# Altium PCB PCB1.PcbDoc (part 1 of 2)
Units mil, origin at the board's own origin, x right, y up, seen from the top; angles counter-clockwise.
Board outline 3935 x 3935 mil, 2 copper layers (Top Layer, Bottom Layer); 151 components, 133 nets, 573 pads, 224 vias.
Unrouted connection lines stored in the file: 1.
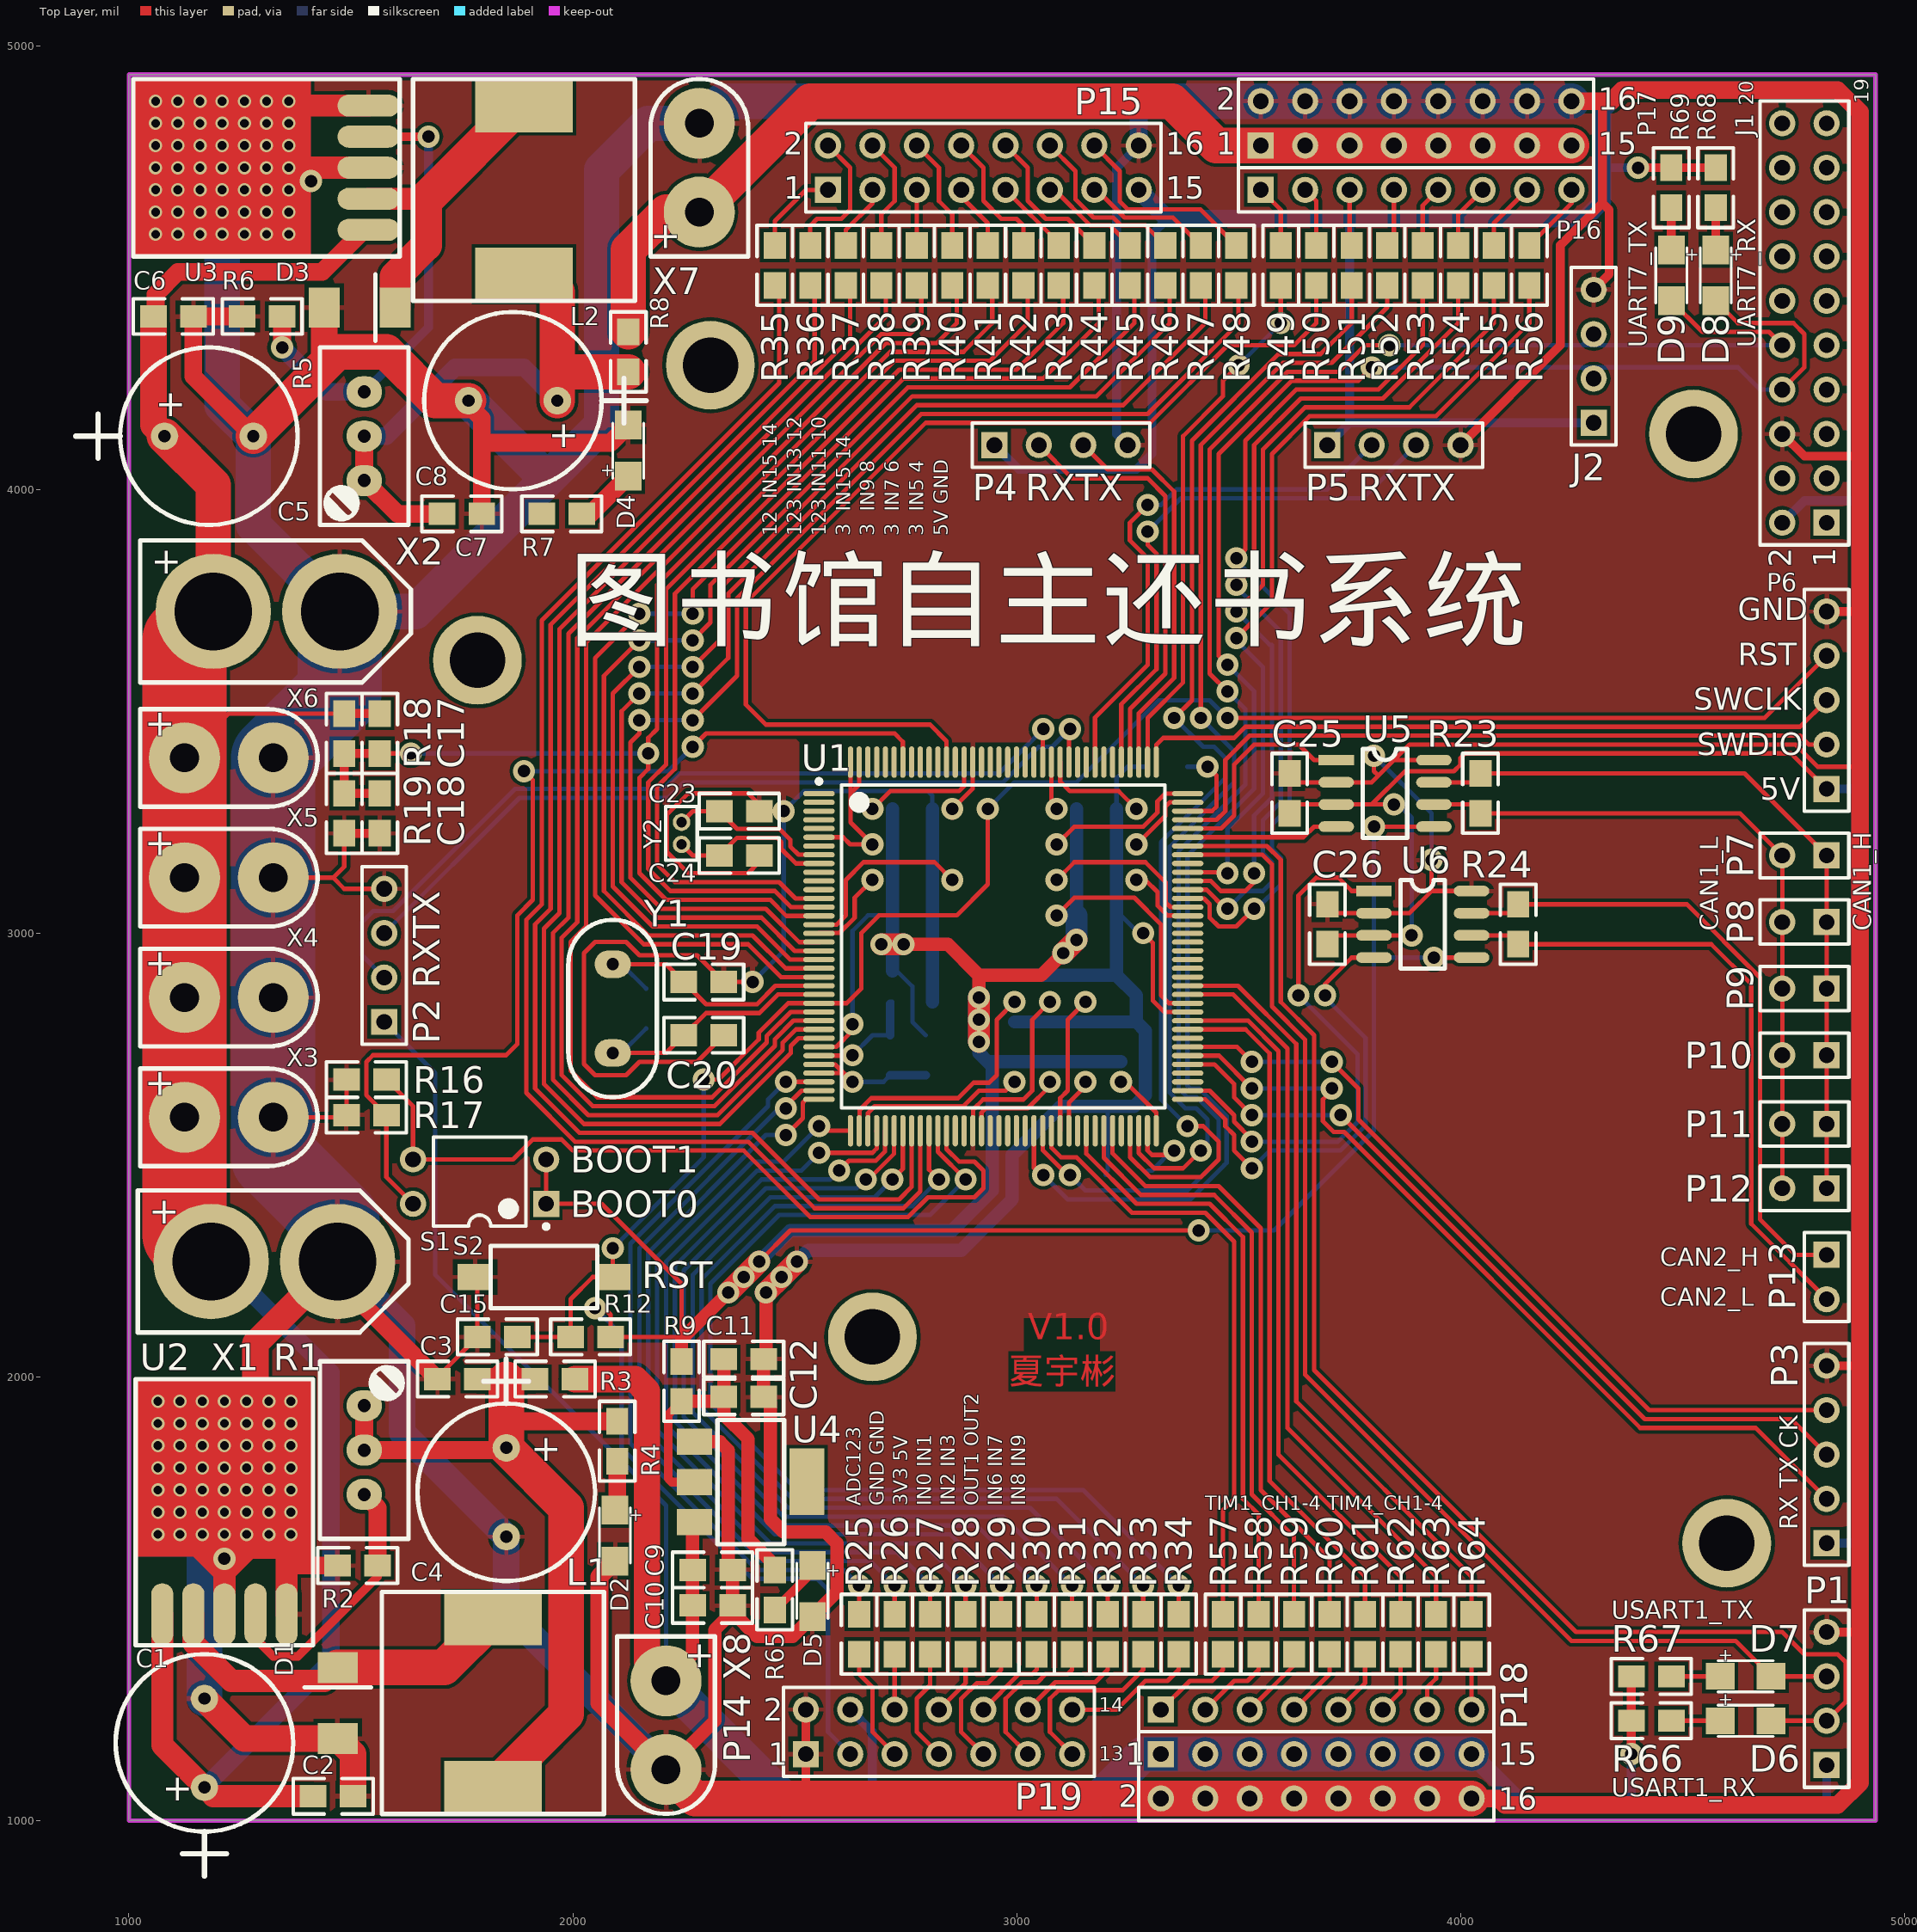
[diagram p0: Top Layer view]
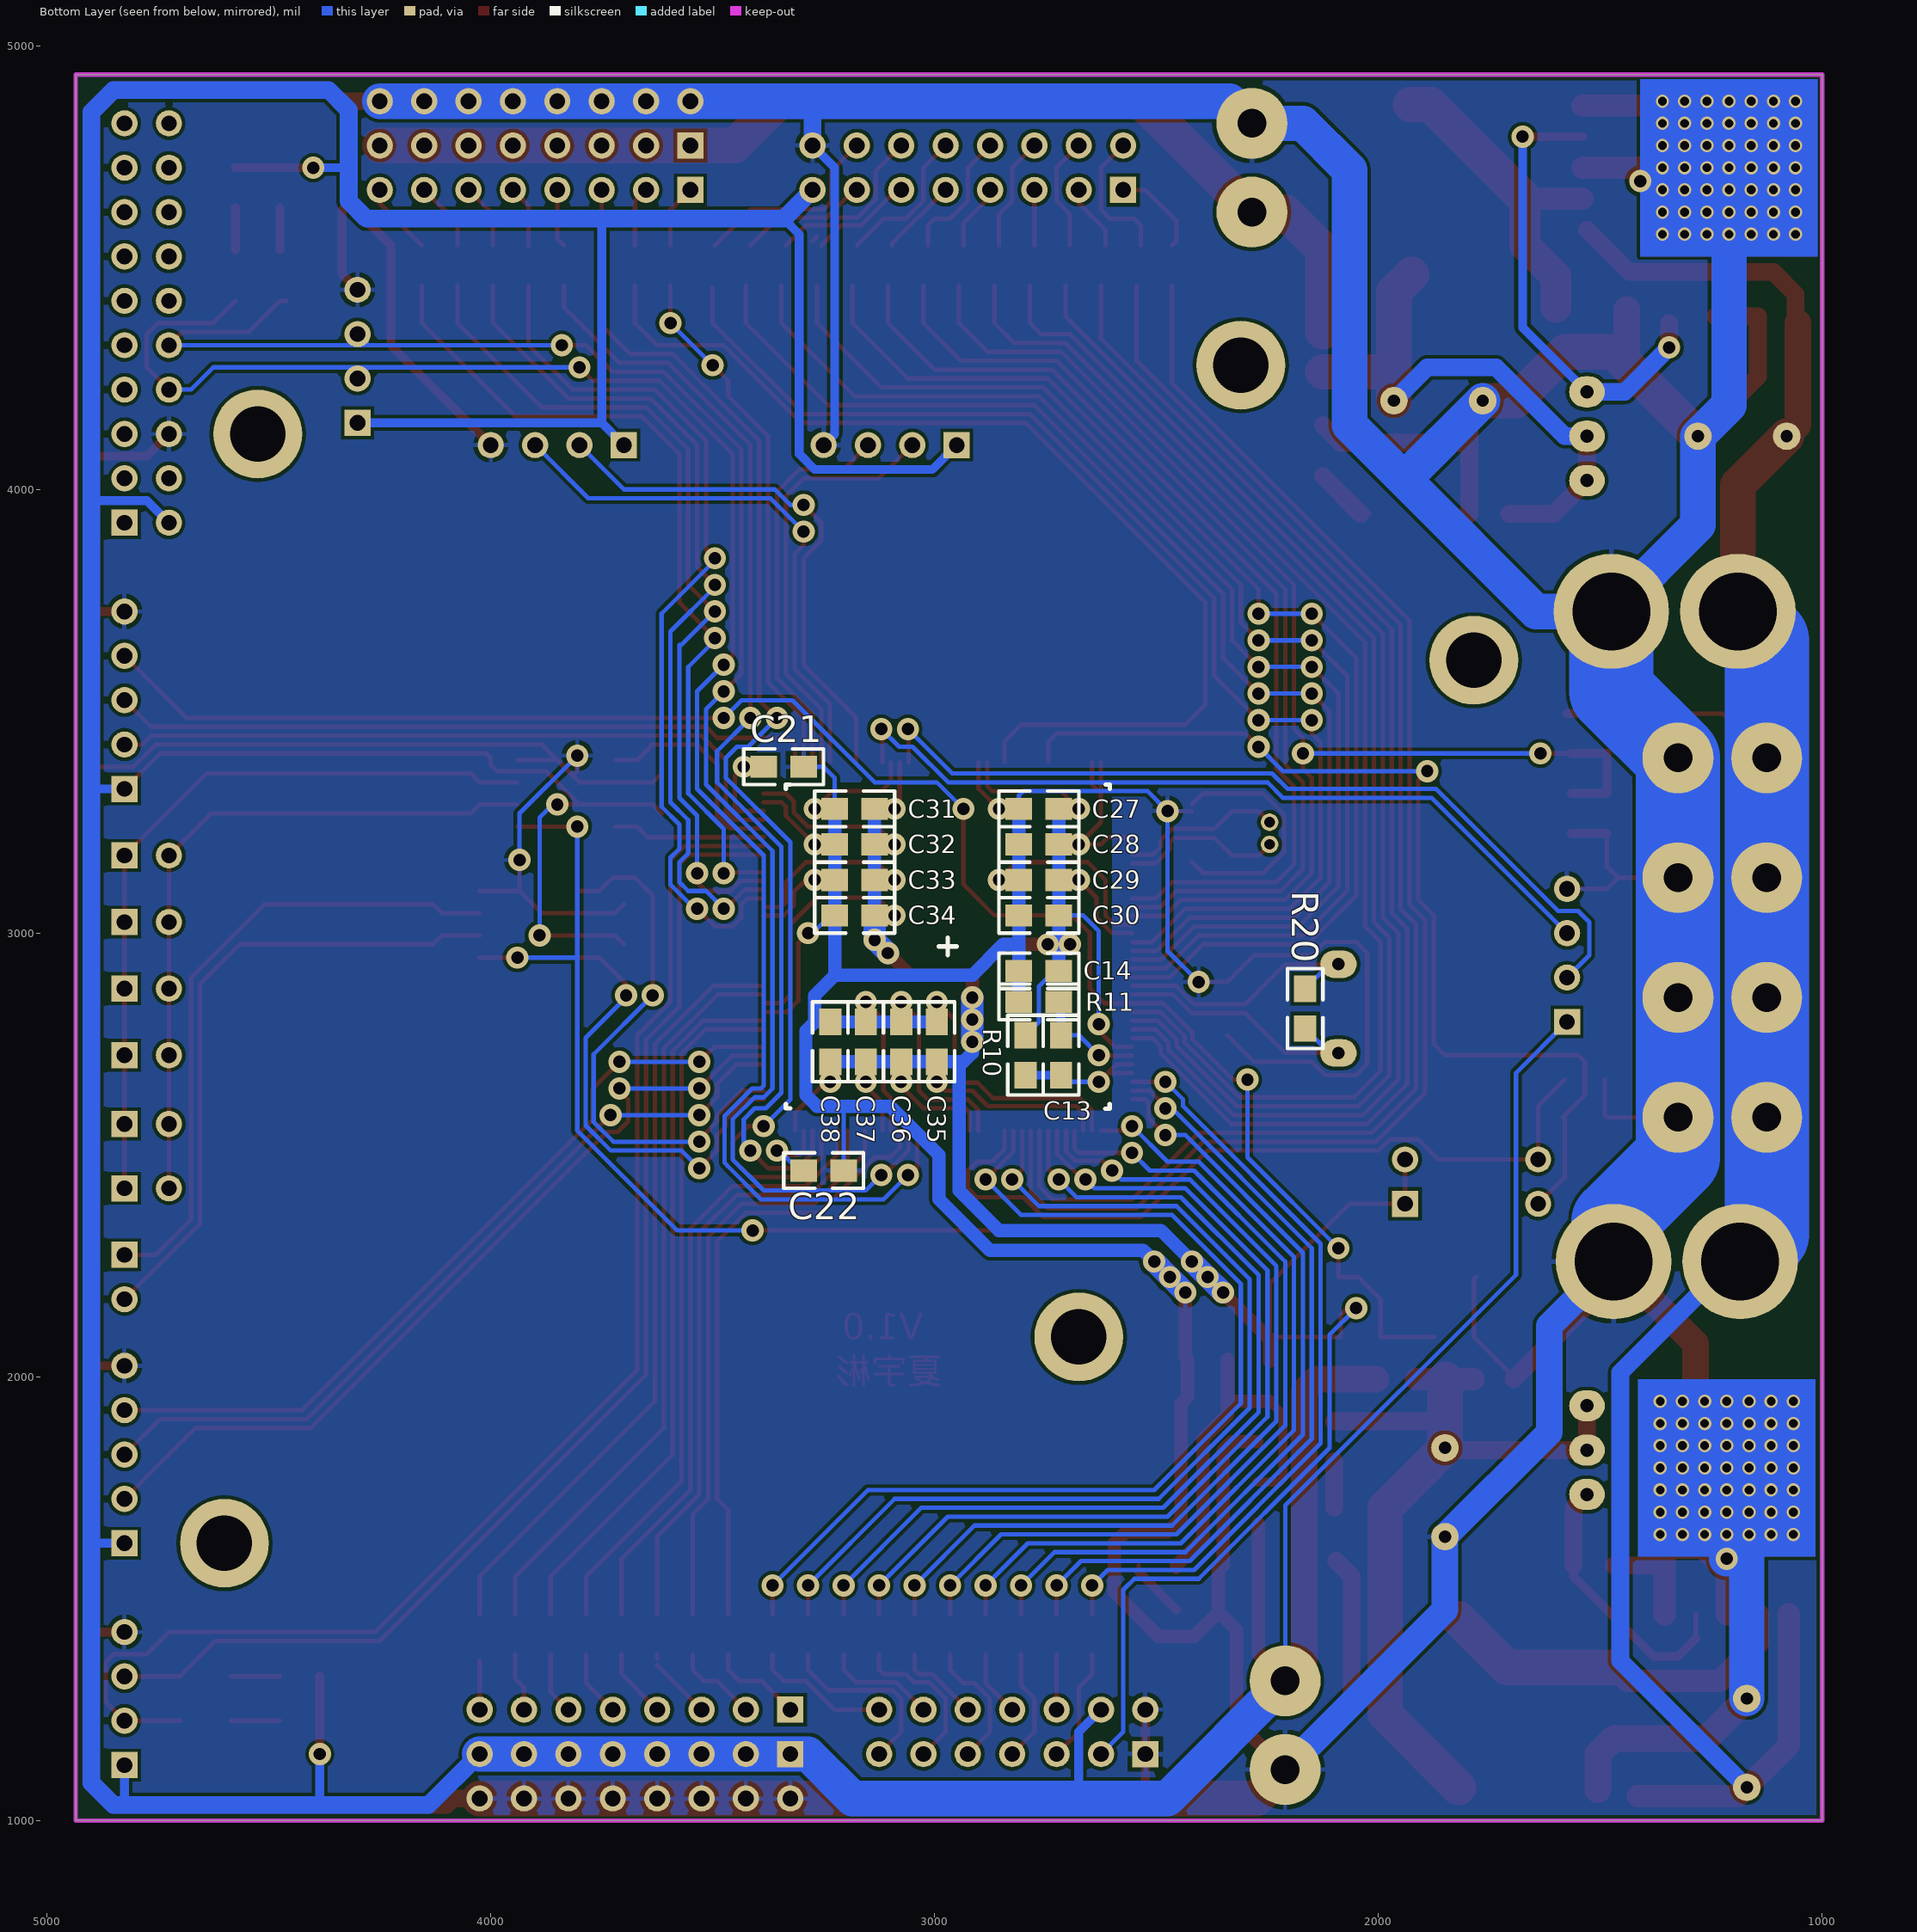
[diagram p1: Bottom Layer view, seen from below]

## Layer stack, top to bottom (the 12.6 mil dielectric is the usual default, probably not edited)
Top Solder: solder mask 0.4, Solder Resist, Dk 3.5
Top Layer: signal copper 1.4
Dielectric 1: dielectric 12.6, FR-4, Dk 4.8
Bottom Layer: signal copper 1.4
Bottom Solder: solder mask 0.4, Solder Resist, Dk 3.5

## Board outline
1000,1000 4935,1000 4935,4935 1000,4935

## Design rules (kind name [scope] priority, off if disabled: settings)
Clearance [All] p1: gap=8
PolygonConnect [All] p1: connectstyle=Relief reliefconductorwidth=10 reliefentries=4 polygonreliefangle="90 Angle" airgapwidth=10
RoutingVias [All] p1: holewidth=28 width=50 viastyle="Through Hole" minholewidth=28 minwidth=50 maxholewidth=28 maxwidth=50
SolderMaskExpansion [All] p1: expansion=4
Width [All] p1: maxlimit=10 minlimit=10 preferedwidth=10
30 further rules are at their usual default settings.

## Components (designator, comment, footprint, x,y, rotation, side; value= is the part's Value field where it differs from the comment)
C1 "Cap Pol1" RB-.2/.4 1170,1075 r270 top
C2 "Cap" 0805 1505,1055 r180 top
C3 "Cap" 0805 1785,1995 r180 top
C4 "Cap Pol1" RB-.2/.4 1850,1840 r90 top
C5 "Cap Pol1" RB-.2/.4 1080,4120 r180 top
C6 "Cap" 0805 1145,4390 r180 top
C7 "Cap" 0805 1705,3945 r0 top
C8 "Cap Pol1" RB-.2/.4 1965,4200 r0 top
C9 "Cap Pol1" 0805 2270,1565 r0 top
C10 "Cap" 0805 2360,1485 r180 top
C11 "Cap Pol1" 0805 2340,2040 r0 top
C12 "Cap" 0805 2430,1955 r180 top
C13 "Cap" 0805 2715,2770 r270 bottom
C14 "Cap" 0805 2810,2915 r180 bottom
C15 "Cap" 0805 1875,2090 r180 top
C17 "Cap" 0805 1565,3405 r90 top
C18 "Cap" 0805 1565,3225 r90 top
C19 "Cap" 0805 2250,2890 r0 top
C20 "Cap" 0805 2250,2770 r0 top
C21 "Cap" 0805 3295,3375 r0 bottom
C22 "Cap" 0805 3205,2465 r0 bottom
C23 "12pF" 0805 2420,3275 r180 top
C24 "12pF" 0805 2420,3175 r180 top
C25 "Cap" 0805 3615,3270 r90 top
C26 "Cap" 0805 3700,2975 r90 top
C27 "Cap" 0805 2810,3280 r180 bottom
C28 "Cap" 0805 2810,3200 r180 bottom
C29 "Cap" 0805 2810,3120 r180 bottom
C30 "Cap" 0805 2810,3040 r180 bottom
C31 "Cap" 0805 3225,3280 r180 bottom
C32 "Cap" 0805 3225,3200 r180 bottom
C33 "Cap" 0805 3225,3120 r180 bottom
C34 "Cap" 0805 3225,3040 r180 bottom
C35 "Cap" 0805 2995,2800 r270 bottom
C36 "Cap" 0805 3075,2800 r270 bottom
C37 "Cap" 0805 3155,2800 r270 bottom
C38 "Cap" 0805 3235,2800 r270 bottom
D1 "SS54" DO-214AA 1515,1150 r90 top
D2 "LED_RED" 1206_LED 2060,1705 r270 top
D3 "SS54" DO-214AA 1405,4365 r0 top
D4 "LED_RED" 1206_LED 2160,4025 r90 top
D5 "LED_RED" 1206_LED 2505,1580 r270 top
D6 "LED_RED" 1206_LED 4580,1190 r0 top
D7 "LED_RED" 1206_LED 4580,1290 r0 top
D8 "LED_RED" 1206_LED 4540,4545 r270 top
D9 "LED_RED" 1206_LED 4440,4545 r270 top
J1 "Header 10X2H" HDR2X10 4825,3925 r90 top
J2 "USART3" HDR1X4 4300,4150 r90 top
L1 "Inductor" 12*12*7贴片电感 1570,1015 r0 top
L2 "Inductor" 12*12*7贴片电感 1640,4425 r0 top
P1 "USART1" HDR1X4 4825,1125 r90 top
P2 "USART2" HDR1X4 1575,2800 r90 top
P3 "Header 5" HDR1X5 4825,1625 r90 top
P4 "USART3" HDR1X4 2950,4100 r0 top
P5 "USART3" HDR1X4 3700,4100 r0 top
P6 "Header 5" HDR1X5 4825,3325 r90 top
P7 "CAN1" HDR1X2 4825,3175 r180 top
P8 "CAN1" HDR1X2 4825,3025 r180 top
P9 "CAN1" HDR1X2 4825,2875 r180 top
P10 "CAN1" HDR1X2 4825,2725 r180 top
P11 "CAN1" HDR1X2 4825,2570 r180 top
P12 "CAN1" HDR1X2 4825,2425 r180 top
P13 "CAN2" HDR1X2 4825,2275 r270 top
P14 "Header 7X2" HDR2X7 2525,1150 r0 top
P15 "Header 8X2" HDR2X8#1 2575,4675 r0 top
P16 "Header 8" HDR1X8 3550,4675 r0 top
P17 "Header 8X2" HDR2X8#1 3550,4775 r0 top
P18 "Header 8" HDR1X8 3325,1250 r0 top
P19 "Header 8X2" HDR2X8#2 3325,1150 r0 top
R1 "Res Tap" 3296 1530,1835 r90 top
R2 "Res2" 0805 1470,1575 r0 top
R3 "Res2" 0805 2100,1900 r270 top
R4 "Res2" 0805 1915,1995 r0 top
R5 "Res Tap" 3296 1530,4120 r270 top
R6 "Res2" 0805 1255,4390 r0 top
R7 "Res2" 0805 1930,3945 r0 top
R8 "Res2" 0805 2125,4265 r90 top
R9 "Res2" 0805 2245,1945 r90 top
R10 "Res2" 0805 2795,2680 r90 bottom
R11 "Res2" 0805 2720,2845 r0 bottom
R12 "Res2" 0805 1995,2090 r0 top
R16 "Res2" 0805 1490,2670 r0 top
R17 "Res2" 0805 1490,2590 r0 top
R18 "9K" 0805 1485,3405 r90 top
R19 "1K" 0805 1485,3225 r90 top
R20 "Res2" 0805 2165,2785 r90 bottom
R23 "Res2" 0805 4045,3270 r90 top
R24 "120R" 0805 4130,2975 r90 top
R25 "100R" 0805 2645,1465 r270 top
R26 "100R" 0805 2725,1375 r90 top
R27 "100R" 0805 2805,1465 r270 top
R28 "100R" 0805 2885,1375 r90 top
R29 "100R" 0805 2965,1465 r270 top
R30 "100R" 0805 3045,1375 r90 top
R31 "100R" 0805 3125,1465 r270 top
R32 "100R" 0805 3205,1375 r90 top
R33 "100R" 0805 3285,1465 r270 top
R34 "100R" 0805 3365,1375 r90 top
R35 "100R" 0805 2455,4460 r90 top
R36 "100R" 0805 2535,4550 r270 top
R37 "100R" 0805 2615,4460 r90 top
R38 "100R" 0805 2695,4550 r270 top
R39 "100R" 0805 2775,4460 r90 top
R40 "100R" 0805 2855,4550 r270 top
R41 "100R" 0805 2935,4460 r90 top
R42 "100R" 0805 3015,4550 r270 top
R43 "100R" 0805 3095,4460 r90 top
R44 "100R" 0805 3175,4550 r270 top
R45 "100R" 0805 3255,4460 r90 top
R46 "100R" 0805 3335,4550 r270 top
R47 "100R" 0805 3415,4460 r90 top
R48 "100R" 0805 3495,4550 r270 top
R49 "100R" 0805 3595,4460 r90 top
R50 "100R" 0805 3675,4460 r90 top
R51 "100R" 0805 3755,4460 r90 top
R52 "100R" 0805 3835,4460 r90 top
R53 "100R" 0805 3915,4460 r90 top
R54 "100R" 0805 3995,4460 r90 top
R55 "100R" 0805 4075,4460 r90 top
R56 "100R" 0805 4155,4460 r90 top
R57 "100R" 0805 3465,1465 r270 top
R58 "100R" 0805 3545,1465 r270 top
R59 "100R" 0805 3625,1465 r270 top
R60 "100R" 0805 3705,1465 r270 top
R61 "100R" 0805 3785,1465 r270 top
R62 "100R" 0805 3865,1465 r270 top
R63 "100R" 0805 3945,1465 r270 top
R64 "100R" 0805 4025,1465 r270 top
R65 "Res2" 0805 2455,1475 r90 top
R66 "Res2" 0805 4475,1225 r180 top
R67 "Res2" 0805 4475,1325 r180 top
R68 "Res2" 0805 4575,4635 r90 top
R69 "Res2" 0805 4475,4635 r90 top
S1 "SW DIP-2" DIP-4 1790,2440 r180 top
S2 "SW-PB" "3*6 开关" 1815,2155 r0 top
U1 "STM32F429ZGT6" STM-LQFP144_N 2970,2970 r0 top locked
U2 "LM2596S-ADJ" TO-263 1015,1395 r0 top
U3 "LM2596S-ADJ" TO-263 1610,4525 r90 top
U4 "AMS1117-3.3V" SOT223 2274,1853.55 r270 top
U5 "MCP2562-E/MF" SO-8 3720,3390 r0 top
U6 "MCP2562-E/MF" SO-8 3805,3095 r0 top
X1 "XT60" XT60PB 1020,2100 r0 top
X2 "XT60" XT60PB 1025,3565 r0 top
X3 "XT30" XT30UPB 1025,2475 r0 top
X4 "XT30" XT30UPB 1025,2745 r0 top
X5 "XT30" XT30UPB 1025,3015 r0 top
X6 "XT30" XT30UPB 1025,3285 r0 top
X7 "XT30" XT30UPB 2395,4525 r90 top
X8 "XT30" XT30UPB 2100,1415 r270 top
Y1 "8MHz" XTAL 2090,2830 r270 top
Y2 "32.768k" MHDR1X2 2245,3200 r90 top

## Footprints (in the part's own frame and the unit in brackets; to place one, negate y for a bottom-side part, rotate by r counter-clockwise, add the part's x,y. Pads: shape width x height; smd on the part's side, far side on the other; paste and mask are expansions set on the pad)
"3*6 开关" [mil]
  rect 80x60 smd: 1(-35,70) 2(275,70)
  silkscreen extent 0,0 240,140
12*12*7贴片电感 [mil]
  rect 220x120 smd: 1(250,440) 2(250,60)
  silkscreen extent 0,0 500,500
0805 [mil]
  rect 60x50 smd: 1(0,0) 2(90,0)
  silkscreen extent -45,-40 135,40
1206_LED [mil]
  rect 65x60 smd: 1(5,35) 2(120,35)
  silkscreen extent 0,0 125,70
3296 [mil]
  oval 70x80 hole 30: 1(-100,0) 2(0,0) 3(100,0)
  silkscreen extent -200,-100 200,100
DIP-4 [mm] "DIP; 4 Leads; Row Spacing 7.62 mm; Pitch 2.54 mm"
  rect 1.5x1.5 hole 0.9: 1(-3.81,1.27)
  round 1.5 hole 0.9: 2(-3.81,-1.27) 3(3.81,-1.27) 4(3.81,1.27)
  silkscreen extent -3.94,-2.55 2.65,2.69, body extent -3.15,-2.5 3.15,2.5, height 5.6
DO-214AA [mil]
  rect 70x90 smd: 1(35,45) 2(195,45)
  silkscreen extent 150,-30 150,120
HDR1X2 [mm] "Connector; Header; 2 Position"
  rect 1.5x1.5 hole 0.9: 1(0,0)
  round 1.5 hole 0.9: 2(2.54,0)
  silkscreen extent -1.27,-1.27 3.81,1.27
HDR1X4 [mm] "Connector; Header; 4 Position"
  rect 1.5x1.5 hole 0.9: 1(0,0)
  round 1.5 hole 0.9: 2(2.54,0) 3(5.08,0) 4(7.62,0)
  silkscreen extent -1.27,-1.27 8.89,1.27
HDR1X5 [mm] "Connector; Header; 5 Position"
  rect 1.5x1.5 hole 0.9: 1(0,0)
  round 1.5 hole 0.9: 2(2.54,0) 3(5.08,0) 4(7.62,0) 5(10.16,0)
  silkscreen extent -1.27,-1.27 11.43,1.27
HDR1X8 [mm] "Connector; Header; 8 Position"
  rect 1.5x1.5 hole 0.9: 1(0,0)
  round 1.5 hole 0.9: 2(2.54,0) 3(5.08,0) 4(7.62,0) 5(10.16,0) 6(12.7,0) 7(15.24,0) 8(17.78,0)
  silkscreen extent -1.27,-1.27 19.05,1.27
HDR2X7 [mm] "Connector; Header; 7x2 Position"
  rect 1.5x1.5 hole 0.9: 1(0,0)
  round 1.5 hole 0.9: 2(0,2.54) 3(2.54,0) 4(2.54,2.54) 5(5.08,0) 6(5.08,2.54) 7(7.62,0) 8(7.62,2.54) 9(10.16,0) 10(10.16,2.54) 11(12.7,0) 12(12.7,2.54) 13(15.24,0) 14(15.24,2.54)
  silkscreen extent -1.27,-1.27 16.51,3.81
HDR2X8#1 [mm] "Connector; Header; 8x2 Position"
  rect 1.5x1.5 hole 0.9: 1(0,0)
  round 1.5 hole 0.9: 2(0,2.54) 3(2.54,0) 4(2.54,2.54) 5(5.08,0) 6(5.08,2.54) 7(7.62,0) 8(7.62,2.54) 9(10.16,0) 10(10.16,2.54) 11(12.7,0) 12(12.7,2.54) 13(15.24,0) 14(15.24,2.54) 15(17.78,0) 16(17.78,2.54)
  silkscreen extent -1.27,-1.27 19.05,3.81
HDR2X8#2 [mm] "Connector; Header; 8x2 Position"
  rect 1.5x1.5 hole 0.9: 1(0,0)
  round 1.5 hole 0.9: 2(0,-2.54) 3(2.54,0) 4(2.54,-2.54) 5(5.08,0) 6(5.08,-2.54) 7(7.62,0) 8(7.62,-2.54) 9(10.16,0) 10(10.16,-2.54) 11(12.7,0) 12(12.7,-2.54) 13(15.24,0) 14(15.24,-2.54) 15(17.78,0) 16(17.78,-2.54)
  silkscreen extent -1.27,-3.81 19.05,1.27
HDR2X10 [mm] "Connector; Header; 10x2 Position"
  rect 1.5x1.5 hole 0.9: 1(0,0)
  round 1.5 hole 0.9: 2(0,2.54) 3(2.54,0) 4(2.54,2.54) 5(5.08,0) 6(5.08,2.54) 7(7.62,0) 8(7.62,2.54) 9(10.16,0) 10(10.16,2.54) 11(12.7,0) 12(12.7,2.54) 13(15.24,0) 14(15.24,2.54) 15(17.78,0) 16(17.78,2.54) 17(20.32,0) 18(20.32,2.54) 19(22.86,0) 20(22.86,2.54)
  silkscreen extent -1.27,-1.27 24.13,3.81
MHDR1X2 [mm] "Connector; Header; 2 Position"
  round 1 hole 0.6: 1(0,0) 2(1.27,0)
  silkscreen extent -0.9,-0.9 2.17,0.9
RB-.2/.4 [mil]
  round 62 hole 28: 1(0,0) 2(-200,0)
  silkscreen extent -300,-200 200,200
SO-8 [mil]
  rect 80x24 smd: 1(0,0)
  oval 80x24 smd: 2(0,-50) 3(0,-100) 4(0,-150) 5(220,-150) 6(220,-100) 7(220,-50) 8(220,0)
  silkscreen extent 60,-175 160,25
SOT223 [mil]
  rect 59x79 smd: 1(0,0) 2(90.55,0) 3(181.1,0)
  rect 150x79 smd: 4(89.88,253.54)
  silkscreen extent -49,52 231,202
STM-LQFP144_N [mm] "Thin QFP, 144-Leads, Body 20x20mm, Pitch 0.5mm, IPC Medium Density"
  oval 1.8x0.3 smd: 1(-10.55,8.75) 2(-10.55,8.25) 3(-10.55,7.75) 4(-10.55,7.25) 5(-10.55,6.75) 6(-10.55,6.25) 7(-10.55,5.75) 8(-10.55,5.25) 9(-10.55,4.75) 10(-10.55,4.25) 11(-10.55,3.75) 12(-10.55,3.25) 13(-10.55,2.75) 14(-10.55,2.25) 15(-10.55,1.75) 16(-10.55,1.25) 17(-10.55,0.75) 18(-10.55,0.25) 19(-10.55,-0.25) 20(-10.55,-0.75) 21(-10.55,-1.25) 22(-10.55,-1.75) 23(-10.55,-2.25) 24(-10.55,-2.75) 25(-10.55,-3.25) 26(-10.55,-3.75) 27(-10.55,-4.25) 28(-10.55,-4.75) 29(-10.55,-5.25) 30(-10.55,-5.75) 31(-10.55,-6.25) 32(-10.55,-6.75) 33(-10.55,-7.25) 34(-10.55,-7.75) 35(-10.55,-8.25) 36(-10.55,-8.75) 73(10.55,-8.75) 74(10.55,-8.25) 75(10.55,-7.75) 76(10.55,-7.25) 77(10.55,-6.75) 78(10.55,-6.25) 79(10.55,-5.75) 80(10.55,-5.25) 81(10.55,-4.75) 82(10.55,-4.25) 83(10.55,-3.75) 84(10.55,-3.25) 85(10.55,-2.75) 86(10.55,-2.25) 87(10.55,-1.75) 88(10.55,-1.25) 89(10.55,-0.75) 90(10.55,-0.25) 91(10.55,0.25) 92(10.55,0.75) 93(10.55,1.25) 94(10.55,1.75) 95(10.55,2.25) 96(10.55,2.75) 97(10.55,3.25) 98(10.55,3.75) 99(10.55,4.25) 100(10.55,4.75) 101(10.55,5.25) 102(10.55,5.75) 103(10.55,6.25) 104(10.55,6.75) 105(10.55,7.25) 106(10.55,7.75) 107(10.55,8.25) 108(10.55,8.75)
  oval 0.3x1.8 smd: 37(-8.75,-10.55) 38(-8.25,-10.55) 39(-7.75,-10.55) 40(-7.25,-10.55) 41(-6.75,-10.55) 42(-6.25,-10.55) 43(-5.75,-10.55) 44(-5.25,-10.55) 45(-4.75,-10.55) 46(-4.25,-10.55) 47(-3.75,-10.55) 48(-3.25,-10.55) 49(-2.75,-10.55) 50(-2.25,-10.55) 51(-1.75,-10.55) 52(-1.25,-10.55) 53(-0.75,-10.55) 54(-0.25,-10.55) 55(0.25,-10.55) 56(0.75,-10.55) 57(1.25,-10.55) 58(1.75,-10.55) 59(2.25,-10.55) 60(2.75,-10.55) 61(3.25,-10.55) 62(3.75,-10.55) 63(4.25,-10.55) 64(4.75,-10.55) 65(5.25,-10.55) 66(5.75,-10.55) 67(6.25,-10.55) 68(6.75,-10.55) 69(7.25,-10.55) 70(7.75,-10.55) 71(8.25,-10.55) 72(8.75,-10.55) 109(8.75,10.55) 110(8.25,10.55) 111(7.75,10.55) 112(7.25,10.55) 113(6.75,10.55) 114(6.25,10.55) 115(5.75,10.55) 116(5.25,10.55) 117(4.75,10.55) 118(4.25,10.55) 119(3.75,10.55) 120(3.25,10.55) 121(2.75,10.55) 122(2.25,10.55) 123(1.75,10.55) 124(1.25,10.55) 125(0.75,10.55) 126(0.25,10.55) 127(-0.25,10.55) 128(-0.75,10.55) 129(-1.25,10.55) 130(-1.75,10.55) 131(-2.25,10.55) 132(-2.75,10.55) 133(-3.25,10.55) 134(-3.75,10.55) 135(-4.25,10.55) 136(-4.75,10.55) 137(-5.25,10.55) 138(-5.75,10.55) 139(-6.25,10.55) 140(-6.75,10.55) 141(-7.25,10.55) 142(-7.75,10.55) 143(-8.25,10.55) 144(-8.75,10.55)
  silkscreen extent -10.67,-9.25 9.25,9.57, body extent -10,-10 10,10, height 1.6
TO-263 [mil]
  oval 50x140 smd: 1(60,70) 2(130,70) 3(200,70) 4(270,70) 5(340,70)
  Top Layer region: 0,200 400,200 400,600 0,600
  Bottom Layer region: 0,200 400,200 400,600 0,600
  silkscreen extent 0,0 400,600
XT30UPB [mil]
  round 160 hole 65: 1(100,110) 2(300,110)
  silkscreen extent 0,0 400,220
XT60PB [mil]
  round 260 hole 175: 1(165,160) 2(450,160)
  silkscreen extent 0,0 610,320
XTAL [mil]
  oval 62x82 hole 28: 1(-100,0) 2(100,0)
  silkscreen extent -200,-100 200,100

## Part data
C1 C4 C5 C8 C9 C11: "Polarized Capacitor (Radial)"
C2 C3 C6 C7 C10 C12 C13 C14 C15 C17 C18 C19 C20 C21 C22 C25 C26 C27 C28 C29 C30 C31 C32 C33 C34 C35 C36 C37 C38: "Capacitor"
C23 C24: library part CAP, "Capcitor"
D1 D3: library part "Diode 11DQ03", "Schottky Rectifier"
D2 D4 D5 D6 D7 D8 D9: library part LED3, "Typical BLUE SiC LED"
J1: "Header, 10-Pin, Dual row, Right Angle"
J2 P1 P2 P4 P5: library part "Header 4", "Header, 4-Pin"
P3 P6: "Header, 5-Pin"
P7 P8 P9 P10 P11 P12 P13 X1 X2 X3 X4 X5 X6 X7 X8: library part "Header 2", "Header, 2-Pin"
P14: "Header, 7-Pin, Dual row"
P15 P17 P19: "Header, 8-Pin, Dual row"
P16 P18: "Header, 8-Pin"
R1 R5: "Tapped Resistor"
R2 R3 R4 R6 R7 R8 R9 R10 R11 R12 R16 R17 R20 R23 R65 R66 R67 R68 R69: "Resistor"
R18 R19 R24 R25 R26 R27 R28 R29 R30 R31 R32 R33 R34 R35 R36 R37 R38 R39 R40 R41 R42 R43 R44 R45 R46 R47 R48 R49 R50 R51 R52 R53 R54 R55 R56 R57 R58 R59 R60 R61 R62 R63 R64: library part Res2, "Resistor"
S1: "DIP Switch, 2 Position, SPST"
S2: "Switch"
U1: "ARM Cortex-M4 32-bit MCU+FPU, 225 DMIPS, 1024 kB Flash, 256 kB Internal RAM, 114 I/Os, 144-pin LQFP, -40 to 85 degC, Tray"
U2 U3: library part LM2576S-5.0, "CI-LM2576S-5.0"
U4: library part 11
Y1: library part XTAL, "Crystal Oscillator"
Y2: library part CRYSTAL, "Crystal 8MHz PLUG"

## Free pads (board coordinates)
  round 200 hole 125: 0(1785,3615) 0(2310,4280) 0(2675,2090) 0(4525,4125) 0(4600,1625)

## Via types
v1: diameter 50, hole 28, Top Layer to Bottom Layer, tented both sides, 126 vias
v2: diameter 30, hole 20, Top Layer to Bottom Layer, tented both sides, 98 vias

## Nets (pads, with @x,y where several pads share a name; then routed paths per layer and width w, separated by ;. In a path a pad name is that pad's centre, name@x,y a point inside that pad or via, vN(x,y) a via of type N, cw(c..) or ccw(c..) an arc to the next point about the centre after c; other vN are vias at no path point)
ADC3_IN4: R48.2 U1.18 | length 2751.3
  Top Layer w10: v1(2150,3480) 2150,3450 2130,3430 2130,3125 2200,3055 2435,3055 2510.16,2979.84 U1.18@2554.65,2979.84 ; v1(2270,3480) 2370,3580 2370,3755 2785,4170 3295,4170 3500,4375 R48.2@3500,4455
  Bottom Layer w10: v1(2150,3480) v1(2270,3480)
ADC3_IN5: R47.1 U1.19 | length 2741.2
  Top Layer w10: v1(2150,3540) 2110,3500 2110,3115 2190,3035 2425,3035 2499.84,2960.16 U1.19@2554.65,2960.16 ; v1(2270,3540) 2350,3620 2350,3765 2775,4190 3240,4190 3425,4375 R47.1@3425,4460
  Bottom Layer w10: v1(2150,3540) v1(2270,3540)
ADC3_IN6: R46.2 U1.20 | length 2721
  Top Layer w10: v1(2150,3600) 2090,3540 2090,3105 2180,3015 2415,3015 2489.53,2940.47 U1.20@2554.65,2940.47 ; v1(2270,3600) 2330,3660 2330,3775 2765,4210 3180,4210 3345,4375 R46.2@3345,4460
  Bottom Layer w10: v1(2150,3600) v1(2270,3600)
ADC3_IN7: R45.1 U1.21 | length 2700.9
  Top Layer w10: v1(2150,3660) 2070,3580 2070,3095 2170,2995 2405,2995 2479.21,2920.79 U1.21@2554.65,2920.79 ; v1(2270,3660) 2310,3700 2310,3785 2755,4230 3120,4230 3265,4375 R45.1@3265,4460
  Bottom Layer w10: v1(2150,3660) v1(2270,3660)
ADC3_IN8: R44.2 U1.22 | length 2680.8
  Top Layer w10: v1(2150,3720) 2050,3620 2050,3085 2160,2975 2395,2975 2468.9,2901.1 U1.22@2554.65,2901.1 ; v1(2270,3720) 2270,3775 2745,4250 3060,4250 3185,4375 R44.2@3185,4460
  Bottom Layer w10: v1(2150,3720) v1(2270,3720)
ADC3_IN9: R43.1 U1.13 | length 2235.7
  Top Layer w10: U1.13@2554.65,3078.27 2501.73,3078.27 2465,3115 2230,3115 2190,3155 2190,3330 2230,3370 2230,3765 2735,4270 3000,4270 3105,4375 R43.1@3105,4460
ADC3_IN14: R42.2 U1.14 | length 2215.5
  Top Layer w10: U1.14@2554.65,3058.58 2491.42,3058.58 2455,3095 2220,3095 2170,3145 2170,3340 2210,3380 2210,3775 2725,4290 2940,4290 3025,4375 R42.2@3025,4460
ADC3_IN15: C17.1 C18.2 R18.1 R19.2 R41.1 U1.15 | length 3050.4
  Top Layer w10: C17.1@1565,3405 v1(1635,3405) ; U1.15@2554.65,3038.9 2481.1,3038.9 2445,3075 2210,3075 2150,3135 2150,3350 2170,3370 v1(2170,3405) 2170,3440 2190,3460 2190,3785 2715,4310 2880,4310 2945,4375 R41.1@2945,4460
  Top Layer w20: C18.2@1565,3315 R19.2@1485,3315 R18.1@1485,3405 C17.1@1565,3405
  Bottom Layer w10: v1(1635,3405) v1(2170,3405)
ADC12_IN6: R31.1 U1.42 | length 2061.9
  Top Layer w10: v1(2660,2445) 2665.91,2445 2723.94,2503.03 U1.42@2723.94,2554.65 ; R31.1@3125,1465 v1(3125,1530)
  Bottom Layer w10: v1(2660,2445) 2640,2425 2435,2425 2250,2240 2250,1910 2475,1685 2970,1685 v1(3125,1530)
ADC12_IN7: R32.2 U1.43 | length 2130
  Top Layer w10: v1(2720,2445) 2743.62,2468.62 U1.43@2743.62,2554.65 ; R32.2@3205,1465 v1(3205,1530)
  Bottom Layer w10: v1(2720,2445) 2680,2405 2445,2405 2270,2230 2270,1920 2485,1705 3030,1705 v1(3205,1530)
ADC12_IN8: R33.1 U1.46 | length 2262.8
  Top Layer w10: U1.46@2802.68,2554.65 2802.68,2467.32 v1(2825,2445) ; R33.1@3285,1465 v1(3285,1530)
  Bottom Layer w10: v1(2825,2445) 2765,2385 2455,2385 2290,2220 2290,1930 2495,1725 3090,1725 v1(3285,1530)
ADC12_IN9: R34.2 U1.47 | length 2367.8
  Top Layer w10: U1.47@2822.36,2554.65 2822.36,2507.64 v1(2885,2445) ; R34.2@3365,1465 v1(3365,1530)
  Bottom Layer w10: v1(2885,2445) 2805,2365 2465,2365 2310,2210 2310,1940 2505,1745 3150,1745 v1(3365,1530)
ADC12_IN14: R36.2 U1.44 | length 3160.9
  Top Layer w10: R36.2@2545,4460 2545,4290 1950,3695 1950,3055 1915,3020 1915,2650 2015,2550 2405,2550 2555,2400 2735,2400 2763.31,2428.31 U1.44@2763.31,2554.65
ADC12_IN15: R35.1 U1.45 | length 3204.2
  Top Layer w10: R35.1@2465,4460 2465,4240 1930,3705 1930,3065 1895,3030 1895,2640 2005,2530 2395,2530 2545,2380 2745,2380 2782.99,2417.99 U1.45@2782.99,2554.65
ADC123_IN0: R25.1 U1.34 | length 1767.1
  Top Layer w10: v1(2480,2664.88) U1.34@2554.65,2664.88 ; R25.1@2645,1465 v1(2645,1530)
  Bottom Layer w10: v1(2480,2664.88) 2480,2645 2470,2655 2440,2625 2440,2610 2130,2300 2130,1850 2415,1565 2610,1565 v1(2645,1530)
ADC123_IN1: R26.2 U1.35 | length 1761.4
  Top Layer w10: v1(2480,2605) 2480,2610 2515.2,2645.2 U1.35@2554.65,2645.2 ; R26.2@2725,1465 v1(2725,1530)
  Bottom Layer w10: v1(2480,2605) 2465,2605 2150,2290 2150,1860 2425,1585 2670,1585 v1(2725,1530)
ADC123_IN2: R27.1 U1.36 | length 1799.1
  Top Layer w10: v1(2480,2545) 2518,2583 2518,2618 2525.51,2625.51 U1.36@2554.65,2625.51 ; R27.1@2805,1465 v1(2805,1530)
  Bottom Layer w10: v1(2480,2545) 2435,2545 2170,2280 2170,1870 2435,1605 2730,1605 v1(2805,1530)
ADC123_IN3: R28.2 U1.37 | length 1857
  Top Layer w10: v1(2555,2565) 2565.35,2554.65 U1.37@2625.51,2554.65 ; R28.2@2885,1465 v1(2885,1530)
  Bottom Layer w10: v1(2555,2565) 2475,2485 2405,2485 2190,2270 2190,1880 2445,1625 2790,1625 v1(2885,1530)
ADC123_IN10: R40.2 U1.26 | length 2870.7
  Top Layer w10: U1.26@2554.65,2822.36 2490.99,2822.36 2437,2768.37 2437,2753.37 2313.63,2630 2055,2630 1995,2690 1995,2980 2030,3015 2030,3655 2705,4330 2820,4330 2865,4375 R40.2@2865,4460
ADC123_IN11: R39.1 U1.27 | length 2850.8
  Top Layer w10: U1.27@2554.65,2802.68 2496.77,2802.68 2455,2760.91 2455,2745.91 2319.09,2610 2045,2610 1975,2680 1975,2990 2010,3025 2010,3665 2695,4350 2760,4350 2785,4375 R39.1@2785,4460
ADC123_IN12: R38.2 U1.28 | length 2823
  Top Layer w10: U1.28@2554.65,2782.99 2502.54,2782.99 2473,2753.46 2473,2737.08 2325.92,2590 2035,2590 1955,2670 1955,3000 1990,3035 1990,3675 2705,4390 R38.2@2705,4460
ADC123_IN13: R37.1 U1.29 | length 2832.4
  Top Layer w10: U1.29@2554.65,2763.31 2508.31,2763.31 2491,2746 2491,2729.62 2331.38,2570 2025,2570 1935,2660 1935,3010 1970,3045 1970,3685 2625,4340 R37.1@2625,4460
BOOT0: R17.2 S1.4 U1.138 | length 2302.5
  Top Layer w10: R17.2@1580,2590 1535,2635 1535,2710 1550,2725 1850,2725 1875,2750 1875,3040 1910,3075 1910,3345 v1(1890,3365) v1@1890,3360 ; R17.2@1585,2585 1580,2580 1580,2450 S1.4@1640,2390 ; v1(2270,3420) 2300,3450 2725,3450 2743.62,3431.38 U1.138@2743.62,3385.35
  Bottom Layer w10: v1(1890,3365) 2215,3365 v1(2270,3420)
BOOT1: R16.2 S1.3 U1.48 | length 1792.1
  Top Layer w10: R16.2@1580,2670 1640,2610 S1.3@1640,2490 1865,2490 1910,2535 1974.54,2535 1997.54,2512 1998,2512 2000,2510 2385,2510 2535,2360 2755,2360 2800,2405 2905,2405 2925,2425 2925,2465 2905,2485 2870.46,2485 2842.05,2513.41 U1.48@2842.05,2554.65
CAN1_H: P7.1 P8.1 P9.1 P10.1 P11.1 P12.1 R23.2 U5.7 | length 1719.9
  Top Layer w10: U5.7@3940,3340 4025,3340 R23.2@4045,3360 4640,3360 P7.1@4825,3175 P8.1@4825,3025 P9.1@4825,2875 P10.1@4825,2725 P11.1@4825,2570 P12.1@4825,2425
CAN1_L: P7.2 P8.2 P9.2 P10.2 P11.2 P12.2 R23.1 U5.6 | length 1582.6
  Top Layer w10: U5.6@3940,3290 4025,3290 R23.1@4045,3270 4630,3270 P7.2@4725,3175 P8.2@4725,3025 P9.2@4725,2875 P10.2@4725,2725 P11.2@4725,2570 P12.2@4725,2425
CAN1_RX: U1.103 U5.4 | length 344.6
  Top Layer w10: U1.103@3385.35,3216.06 3646.06,3216.06 3670,3240 U5.4@3720,3240
CAN1_TX: U1.104 U5.1 | length 492.8
  Top Layer w10: U1.104@3385.35,3235.75 3460.75,3235.75 3490,3265 3490,3380 3535,3425 3640,3425 ; 3640,3420 3670,3390 U5.1@3720,3390
CAN2_H: P13.1 R24.2 U6.7 | length 1454.8
  Top Layer w10: U6.7@4025,3045 4110,3045 R24.2@4130,3065 4510,3065 4675,2900 4675,2355 4755,2275 P13.1@4825,2275
CAN2_L: P13.2 R24.1 U6.6 | length 1456
  Top Layer w10: U6.6@4025,2995 4110,2995 R24.1@4130,2975 4565,2975 4655,2885 4655,2345 P13.2@4825,2175
CAN2_RX: U1.73 U6.4 | length 1025.2
  Top Layer w10: U1.73@3385.35,2625.51 3424.49,2625.51 3470,2580 3470,2565 3490,2545 3490,2510 v1(3530,2470) ; v1(3695,2860) 3695,2885 3755,2945 U6.4@3805,2945
  Bottom Layer w10: v1(3530,2470) 3570,2510 3729.2,2510 3786,2566.8 3786,2764 3695,2855 v1(3695,2860)
CAN2_TX: U1.74 U6.1 | length 1225.2
  Top Layer w10: U1.74@3385.35,2645.2 3434.8,2645.2 3490,2590 3490,2575 3530,2535 v1(3530,2530) ; v1(3635,2860) 3635,3085 3675,3125 3725,3125 3755,3095 U6.1@3805,3095
  Bottom Layer w10: v1(3530,2530) 3723.74,2530 3768,2574.26 3768,2727 v1(3635,2860)
DAC_OUT1: R29.1 U1.40 | length 1960.3
  Top Layer w10: v1(2555,2505) 2675,2505 2684.57,2514.57 U1.40@2684.57,2554.65 U1.40@2683.79,2553.87 ; R29.1@2965,1465 v1(2965,1530)
  Bottom Layer w10: v1(2555,2505) 2515,2465 2415,2465 2210,2260 2210,1890 2455,1645 2850,1645 v1(2965,1530)
DAC_OUT2: R30.2 U1.41 | length 2011
  Top Layer w10: v1(2600,2465) 2622,2487 2682.46,2487 2703.47,2508.02 2703.47,2554.65 U1.41@2704.25,2554.65 ; R30.2@3045,1465 v1(3045,1530)
  Bottom Layer w10: v1(2600,2465) 2580,2445 2425,2445 2230,2250 2230,1900 2465,1665 2910,1665 v1(3045,1530)
GND: C1.2 C2.1 C3.2 C4.2 C5.2 C6.1 C7.2 C8.2 C9.2 C10.1 C11.2 C12.1 C14.1 C15.2 C18.1 C19.2 C20.2 C21.1 C22.1 C23.1 C24.1 C25.2 C26.2 C27.1 C28.1 C29.1 C30.1 C31.1 C32.1 C33.1 C34.1 C35.1 C36.1 C37.1 C38.1 D1.1 D2.2 D3.1 D4.2 D5.2 J1.6 J2.4 P1.4 P2.4 P3.5 P4.4 P5.4 P6.5 P14.1 P14.2 P15.16 P17.2 P17.4 P17.6 P17.8 P17.10 P17.12 P17.14 P17.16 P19.2 P19.4 P19.6 P19.8 P19.10 P19.12 P19.14 P19.16 R2.1 R6.1 R11.2 R16.1 R17.1 R19.1 S2.1 U1.16 U1.38 U1.51 U1.61 U1.83 U1.94 U1.107 U1.120 U1.130 U2.3 U2.5 U3.3 U3.5 U4.1 U5.2 U5.8 U6.2 U6.8 X1.2 X2.2 X3.2 X4.2 X5.2 X6.2 X7.2 X8.2 | length 36614.2
  Top Layer w10: v1(1215,1590) v1@1215,1610 ; X3.2@1325,2585 1485,2585 R17.1@1490,2590 R16.1@1490,2670 ; X5.2@1325,3125 1460,3125 ; X1.2@1470,2220 X1.2@1470,2260 ; R19.1@1485,3225 1485,3150 1460,3125 ; P2.4@1575,3100 1485,3100 1460,3125 ; C3.2@1695,1995 1695,2000 C15.2@1785,2090 1785,2220 S2.1@1780,2225 ; C20.2@2340,2770 2280,2710 2150,2710 2120,2680 2050,2680 2025,2705 2025,2955 2050,2980 2120,2980 2150,2950 2280,2950 C19.2@2340,2890 v1(2405,2890) ; C24.1@2420,3160 2395,3135 2260,3135 2212.31,3182.69 2212.31,3267.31 2260,3315 2395,3315 C23.1@2420,3290 ; C23.1@2420,3275 v1(2475,3275) ; U1.16@2554.65,3019.21 2594.21,3019.21 2615,3040 2615,3120 2655,3160 2815,3160 v1(2855,3120) ; U1.38@2645.2,2554.65 2645.98,2554.65 2645.98,2601.43 2672.54,2628 2868,2628 2903,2663 2938,2663 2955,2680 2955,2805 v1(2995,2845) ; v1@2855,3260 2855,3279.54 2901.1,3325.65 U1.130@2901.1,3385.35 ; U1.51@2901.1,2554.65 2901.88,2555.43 2901.88,2602.34 2924.54,2625 3015,2625 3035,2645 3035,2805 v1(3075,2845) ; U1.61@3097.95,2554.65 3097.95,2627.95 3115,2645 3115,2805 v1(3155,2845) ; U1.120@3097.95,3385.35 3097.95,3342.05 3120,3320 3230,3320 v1(3270,3280) ; v1@3270.23,3199.77 3335,3264.54 3335,3285 3344.8,3294.8 U1.107@3385.35,3294.8 ; v1@3275,3120 3290,3120 3317.55,3092.45 3317.55,3062 3339.87,3039.68 3384.57,3039.68 U1.94@3385.35,3038.9 ; v1(3285,3000) 3307,2978 3307,2848 3332.64,2822.36 U1.83@3385.35,2822.36 ; C25.2@3615,3360 3635,3340 U5.2@3720,3340 3800,3340 3815,3355 ; C26.2@3700,3065 3720,3045 U6.2@3805,3045 3885,3045 3935,3095 ; v1(3805,3400) 3805,3365 3815,3355 ; v1@3815,3390 v1@3823.75,3390 ; v1(3935,3165) 3935,3095 ; U5.8@3940,3390 3850,3390 ; U6.8@4025,3095 3935,3095 ; 4900,3375 4805,3375 4755,3425 3885,3425 3850,3390 ; 3815,3355 3850,3390
  Top Layer w20: R19.1@1485,3225 C18.1@1565,3225 ; C10.1@2360,1470 C10.1@2360,1485 ; 2525,1050 P14.1@2525,1150 P14.2@2525,1250 ; P5.4@4000,4100 4225,4325 4225,4550 4320,4645 ; J2.4@4300,4450 4335,4485 4335,4630 4320,4645 ; 4320,4875 4320,4645 ; J1.6@4725,4125 4775,4075 4900,4075 ; P1.4@4825,1425 4900,1425 ; P3.5@4825,2025 4900,2025 ; P6.5@4825,3725 4900,3725
  Top Layer w30: X8.2@2210,1115 2320,1225 2320,1430 2360,1470 2415,1415 2495,1415 D5.2@2540,1460 2595,1515 2595,1625 2570,1650 2475,1650 2445,1680 2445,1940 C12.1@2430,1955 C11.2@2430,2040 2435,2045 v1(2435,2190) ; U4.1@2274,1853.55 2331.45,1853.55 2350,1835 2350,1575 C9.2@2360,1565 C10.1@2360,1485
  Top Layer w40: R6.1@1240,4390 C6.1@1145,4390 1145,4255 C5.2@1280,4120 ; 1355,1575 R2.1@1470,1575 ; 1390,4725 1390,4865 ; X1.2@1470,2220 C3.2@1695,1995 ; C8.2@1765,4200 1765,4190 1795,4160 1795,4105 ; C7.2@1795,3945 1795,4105 ; D2.2@2095,1585 2060,1550 2060,1265 X8.2@2210,1115 ; D4.2@2125,4145 2085,4105 1795,4105 ; P19.16@4025,1050 4085,1050 4100,1035 4850,1035 4900.53,1085.53 4900.53,1424.47 4900,1425 4900,2025 4900,3375 4900,3725 4900,4075 4900,4850 4850,4900 4365,4900 4340,4875 4320,4875 P17.16@4250,4875
  Top Layer w50: U2.3@1215,1465 1215,1560 1270,1615 1355,1615 1355,1575 U2.5@1355,1465 ; 1390,4725 U3.3@1540,4725 ; 1390,4865 U3.5@1540,4865 ; v1(2435,2190) v1(2470,2225) v1(2505,2260)
  Top Layer w60: C1.2@1170,1275 1260,1185 D1.1@1470,1185 1505,1150 C2.1@1505,1070 ; 1285,1680 1285,2075 X1.2@1470,2260 ; 1440,4280 D3.1@1440,4405
  Top Layer w80: C5.2@1280,4120 1440,4280 1470,4310 1580,4310 1690,4200 C8.2@1765,4200 ; X8.2@2210,1115 2275,1050 2525,1050 P19.2@3325,1050 P19.4@3425,1050 P19.6@3525,1050 P19.8@3625,1050 P19.10@3725,1050 P19.12@3825,1050 P19.14@3925,1050 P19.16@4025,1050
  Bottom Layer w10: 1210,4545 1260,4545 v1(1410,4695) ; 1940,4020 1940,4025 ; v1(2405,2890) 2475,2960 v1(2475,3275) 2520,3320 2800,3320 2810,3310 C27.1@2810,3280 ; C22.1@3200,2455 C22.1@3205,2455 ; C22.1@3205,2465 3205,2610 ; C34.1@3225,3040 3235,3040 3275,3000 v1(3285,3000) ; C31.1@3225,3280 3225,3350 3250,3375 C21.1@3295,3375 ; v1(3805,3400) 3935,3270 v1(3935,3165)
  Bottom Layer w20: P4.4@3250,4100 3225,4125 3225,4725 P15.16@3275,4775
  Bottom Layer w30: v1(2470,2225) 2470,2220 2475,2225 v1@2472.5,2227.5 ; v1(2505,2260) 2530,2285 2875,2285 2990,2400 2990,2500 3100,2610 3205,2610 3265,2610 3290,2635 3290,2780 3270,2800 ; R11.2@2810,2845 C14.1@2810,2915 2810,2975 ; C27.1@2810,3280 C28.1@2810,3200 C29.1@2810,3120 C30.1@2810,3040 2810,2975 ; C35.1@2995,2800 C36.1@3075,2800 C37.1@3155,2800 C38.1@3235,2800 3270,2800 ; C31.1@3225,3280 C32.1@3225,3200 C33.1@3225,3120 C34.1@3225,3040 3225,2905 ; 2810,2975 2845,2975 2915,2905 3225,2905 ; 3225,2905 3270,2860 3270,2800
  Bottom Layer w40: P15.16@3275,4775 3275,4835
  Bottom Layer w50: v1(2435,2190) v1(2470,2225) ; v1@2472.5,2227.5 v1(2505,2260)
  Bottom Layer w60: X1.2@1470,2260 1615,2115 1615,1875 C4.2@1850,1640 1850,1475 X8.2@2210,1115
  Bottom Layer w80: C1.2@1170,1275 1170,1590 v1(1215,1590) ; 1210,4545 1210,4190 C5.2@1280,4120 1280,3920 X2.2@1475,3725 1645,3725 1940,4020 2065,4145 2065,4720 2170,4825 X7.2@2285,4825 2335,4875 P17.2@3550,4875 P17.4@3650,4875 P17.6@3750,4875 P17.8@3850,4875 P17.10@3950,4875 P17.12@4050,4875 P17.14@4150,4875 P17.16@4250,4875 ; C8.2@1765,4200 1940,4025
  Bottom Layer w190: X1.2@1470,2260 1470,2350 1325,2495 X3.2@1325,2585 X4.2@1325,2855 X5.2@1325,3125 X6.2@1325,3395 1475,3545 X2.2@1475,3725
  other v1: 3270,3120 3270,3200 2855,3280
NetC3_1: C3.1 C4.1 L1.2 R1.2 R1.3 R3.1 R4.1 | length 1860.5
  Top Layer w10: C4.1@1845,1835 C4.1@1850,1840
  Top Layer w40: R1.3@1530,1935 R1.2@1530,1835 C4.1@1845,1835 ; 1850,1900 R3.1@2100,1900
  Top Layer w50: C3.1@1785,1995 1850,1995 R4.1@1915,1995
  Top Layer w80: L1.2@1820,1075 1985,1240 1985,1705 C4.1@1850,1840 1850,1900 1850,1995
  Bottom Layer w10: R1.2@1525,1830 R1.2@1530,1835 ; C4.1@1845,1835 C4.1@1850,1840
